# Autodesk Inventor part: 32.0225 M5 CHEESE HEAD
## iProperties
Created: 2012-10
Part Number: 32.0225 M5 CHEESE HEAD
Document SubType Name: Modeling
Designer: Administrator
Density: 7.85 g/cm^3
Material: Steel
Mass: 4.28013 g
Surface Area: 5.33091 cm^2
Volume: 0.545239 cm^3
Author: Administrator
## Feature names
1. Base1
